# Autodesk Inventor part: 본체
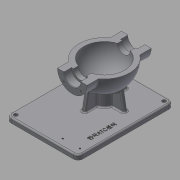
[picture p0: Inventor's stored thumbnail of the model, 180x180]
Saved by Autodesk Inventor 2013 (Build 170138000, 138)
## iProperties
Created: 2015-12
Part Number: 본체
Material: 일반
Document SubType Name: Modeling
Designer: mduedu
Density: 2.71 g/cm^3
Author: mduedu
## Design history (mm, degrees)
sketch "스케치1"
  geometry: L1 (-53, 0)-(53, 0); A1 r 53 centre (0, 0) between (53, 0) and (-53, 0); 2 further points
  constraints: 2 coincident, 2 end point, 2 point on circle, 1 centre point, 1 horizontal, 1 midpoint
  dimensions: "d0" = 53 radius of A1
revolve "회전1" sketch "스케치1" stored, may be unused: angle "d2" = 90 deg
feature "쉘1" dims "d11" = 10
node "작업 평면1"
sketch "스케치2"
  geometry: C1 r 31 at (0, 0); 1 further point
  constraints: 1 centre point, 1 coincident
  dimensions: "d4" = 62 diameter of C1
extrude "돌출1" join sketch "스케치2" stored distance "d5" = 10; taper "d6" = 0 deg
hole "구멍1" diameter "d14" = 35; stored, may be unused: countersink angle "d18" = 90 deg, drill point angle "d20" = 0 deg; dims "d12" = 10, "d13" = 10, "d15" = 6, "d16" = 4, "d17" = 2, "d19" = 16
hole "구멍2" diameter "d23" = 27; stored, may be unused: countersink angle "d27" = 90 deg, drill point angle "d29" = 0 deg; dims "d21" = 10, "d22" = 10, "d24" = 6, "d25" = 4, "d26" = 2, "d28" = 16
fillet "모깎기1" dims "d30" = 0.3
chamfer "모따기1" distance "d40" = 1; stored, may be unused: second distance "d41" = 2, angle "d42" = 45 deg
sketch "스케치4"
  geometry: L1 (0, 0)-(0, -25); L2 (0, 0)-(-17.678, -17.678); A1 r 25 centre (0, 0) between (-17.678, -17.678) and (0, -25); 1 further point
  constraints: 4 end point, 2 point on circle, 1 centre point, 1 coincident, 1 vertical
  dimensions: "d43" = 50 diameter of A1; "d47" = 45 deg angle of L1 L2
hole "구멍4" sketch "스케치4" at (-17.678, -17.678) diameter "d49" = 3.242; stored, may be unused: countersink angle "d53" = 90 deg, drill point angle "d55" = 118 deg; dims "d50" = 11, "d51" = 4, "d52" = 2, "d54" = 13
node "작업 평면3"
sketch "스케치6" dims "d22" = 10
  geometry: L1 (-70, -75)-(130, -75); L2 (130, -75)-(130, 75); L3 (130, 75)-(-70, 75); L4 (-70, 75)-(-70, -75); 2 further points
  constraints: 8 end point, 2 parallel, 1 coincident, 1 horizontal, 1 perpendicular
  dimensions: "d158" = 200 distance of L3.end L2.end; "d159" = 150 distance of L2.end L1.end; "d162" = 75 distance from line of L1 point (0, 0); "d163" = 70 distance from line of L4 point (0, 0)
extrude "돌출3" join sketch "스케치6" distance "d80" = 10; taper "d81" = 0 deg
sketch "스케치7"
  geometry: C1 r 20 at (0, 0); 2 further points
  constraints: 2 coincident, 1 centre point
  dimensions: "d82" = 40 diameter of C1
extrude "돌출4" join sketch "스케치7" stored distance "d84" = 10; taper "d85" = 0 deg
sketch "스케치8"
  geometry: 3 further points
  constraints: 2 coincident
hole "구멍6" sketch "스케치8" at (0, 0) diameter "d86" = 20; stored, may be unused: countersink angle "d90" = 90 deg, drill point angle "d92" = 118 deg; dims "d87" = 7, "d88" = 40, "d89" = 5, "d91" = 10
fillet "모깎기2" dims "d93" = 0.3
sketch "스케치9"
  geometry: L1 (-45, -75)-(-38.245, -36.692); L2 (70, -75)-(-130, -75) reference; A1 r 53 centre (0, 0) between (42.988, 31) and (42.988, -31) reference; 1 further point
  constraints: 2 end point, 1 coincident, 1 point on circle, 1 point on line
  dimensions: "d94" = 45 horizontal distance of L1.start point (0, 0); "d160" = 80 deg angle of L2 L1
feature "리브1" sketch "스케치9" dims "d96" = 1, "d97" = 8, "d98" = 0, "d99" = 0, "d100" = 1, "d101" = 1
fillet "모깎기3" dims "d120" = 3
fillet "모깎기4" dims "d121" = 3, "d122" = 3
fillet "모깎기5" dims "d123" = 3
sketch "스케치12"
  geometry: L1 (0, 100)-(0, -100); L2 (0, 100)-(100, 100); L3 (100, 100)-(100, -100); L4 (100, -100)-(0, -100); 2 further points
  constraints: 8 end point, 3 perpendicular, 1 coincident, 1 midpoint, 1 vertical
  dimensions: "d127" = 200 distance of L2.end L3.end; "d129" = 100 distance between parallel lines of L1 L3
extrude "돌출5" cut sketch "스케치12" stored distance "d130" = 10; taper "d131" = 0 deg
fillet "모깎기10" dims "d164" = 10
fillet "모깎기11" dims "d165" = 3
sketch "스케치15"
  geometry: C1 r 4 at (-120, 65); C2 r 4 at (60, 65); C3 r 4 at (60, -65); A1 r 10 centre (-120, 65) between (-120, 75) and (-130, 65) reference; A2 r 10 centre (60, 65) between (70, 65) and (60, 75) reference; A3 r 10 centre (60, -65) between (60, -75) and (70, -65) reference; 1 further point
  constraints: 3 centre point, 3 coincident, 2 equal radius
  dimensions: "d166" = 8 diameter of C1
extrude "돌출8" cut sketch "스케치15" stored distance "d167" = 10; taper "d168" = 0 deg
sketch "스케치16"
  geometry: L1 (-130, 65)-(-130, -65) reference; L2 (-120, -75)-(60, -75) reference; 2 further points
  constraints: 1 other
  dimensions: "d169" = 70 distance from line of point (-60, -55) L1; "d170" = 20 distance from line of point (-60, -55) L2
feature "엠보싱2" sketch "스케치16" dims "d171" = 0.5, "d172" = 0
sketch "스케치17"
  geometry: L1 (-120, 75)-(60, 75) reference; L2 (-130, -65)-(-130, 65) reference; 2 further points
  constraints: 1 vertical alignment
  dimensions: "d180" = 12 distance from line of L1 point (-114, 63); "d181" = 16 distance from line of point (-114, 63) L2; "d182" = 36 distance of point (-114, 27) point (-114, 63)
hole "구멍9" sketch "스케치17" at (-114, 63), (-114, 27) diameter "d173" = 3.242; stored, may be unused: countersink angle "d177" = 90 deg, drill point angle "d179" = 0 deg; dims "d174" = 6, "d175" = 4, "d176" = 2, "d178" = 8
node "솔리드1"
mirror "대칭1"
mirror "대칭2"
pattern_circular "원형 패턴1" dims angle "d57" = 360 deg
mirror "대칭3"
pattern_circular "원형 패턴3" dims angle "d103" = 360 deg
other parameters: "d3" = 67, "d77" = -85
